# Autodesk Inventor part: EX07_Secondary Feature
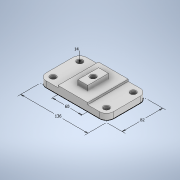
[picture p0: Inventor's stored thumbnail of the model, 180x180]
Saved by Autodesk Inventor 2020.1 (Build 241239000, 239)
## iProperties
Created: 2019-10
Part Number: EX07_Secondary Feature
Material: Generic
Document SubType Name: Modeling
Designer: Synergysoft Dell02
Density: 1 g/cm^3
Appearance: Default
Author: Synergysoft Dell02
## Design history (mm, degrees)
sketch "Sketch1"
  geometry: L1 (54, -41)-(-54, -41); L2 (-68, -27)-(-68, 27); L3 (-54, 41)-(54, 41); L4 (68, 27)-(68, -27); L5 (68, -41)-(-68, 41); L6 (-68, -41)-(68, 41); L7 (30, -41)-(-30, -41); L8 (-30, -41)-(-30, 41); L9 (-30, 41)-(30, 41); L10 (30, 41)-(30, -41); L11 (30, -41)-(-30, 41); L12 (-30, -41)-(30, 41); A1 r 14 centre (54, -27) between (54, -41) and (68, -27); A2 r 14 centre (-54, -27) between (-68, -27) and (-54, -41); A3 r 14 centre (-54, 27) between (-54, 41) and (-68, 27); A4 r 14 centre (54, 27) between (68, 27) and (54, 41); 4 further points
  constraints: 24 end point, 9 point on line, 8 point on circle, 8 tangent, 4 centre point, 4 midpoint, 4 parallel, 3 equal radius, 2 horizontal, 2 perpendicular
  dimensions: "d0" = 136 distance of L5.end L6.end; "d1" = 82 distance of L6.start L5.end; "d2" = 60 distance of L8.end L9.end; "d3" = 14 radius of A1
extrude "Extrusion1" new body sketch "Sketch1" distance "d4" = 12; taper "d5" = 0 deg
extrude "Extrusion2" join sketch "Sketch1" distance "d6" = 16; taper "d7" = 0 deg
sketch "Sketch3"
  geometry: L1 (-30, 41)-(-30, -41) reference; L2 (-30, -41)-(30, -41) reference; L3 (30, -41)-(30, 41) reference; L4 (30, 41)-(-30, 41) reference; L5 (-10, 21)-(-10, -21); L6 (-10, -21)-(10, -21); L7 (10, -21)-(10, 21); L8 (10, 21)-(-10, 21); 1 further point
  constraints: 8 end point, 3 other
  dimensions: "d23" = 20 distance between parallel lines of L4 L8
extrude "Extrusion6" new body sketch "Sketch3" distance "d26" = 10; taper "d28" = 0 deg; dims "d27" = 10, "d29" = 0
sketch "Sketch4"
  geometry: C1 r 5 at (0, 0); 1 further point
  constraints: 1 centre point, 1 coincident
  dimensions: "d30" = 10 diameter of C1
extrude "Extrusion7" cut sketch "Sketch4" stored distance "d31" = 10; taper "d32" = 0 deg
fillet "Fillet1" dims "d33" = 1
chamfer "Chamfer1" distance "d34" = 1; stored, may be unused: second distance "d35" = 2, angle "d36" = 45 deg
body "Solid1"
sketch "Sketch2"
  geometry: L1 (-68, 27)-(-68, -27) reference; L2 (-30, 41)-(-54, 41) reference; C1 r 5 at (-54, 27); C2 r 5 at (54, 27); C3 r 5 at (-54, -27); C4 r 5 at (54, -27); 1 further point
  constraints: 4 centre point, 1 horizontal, 1 vertical, 6 other
  dimensions: "d8" = 10 diameter of C1; "d9" = 14 distance from line of C1.centre L1; "d10" = 14 distance from line of L2 C1.centre; "d13" = 108 distance of C1.centre C2.centre; "d16" = 54 distance of C1.centre C3.centre
extrude "Extrusion3" cut sketch "Sketch2" distance "d21" = 12; taper "d22" = 0 deg
node "Projected Loop1"
body "Solid3"
